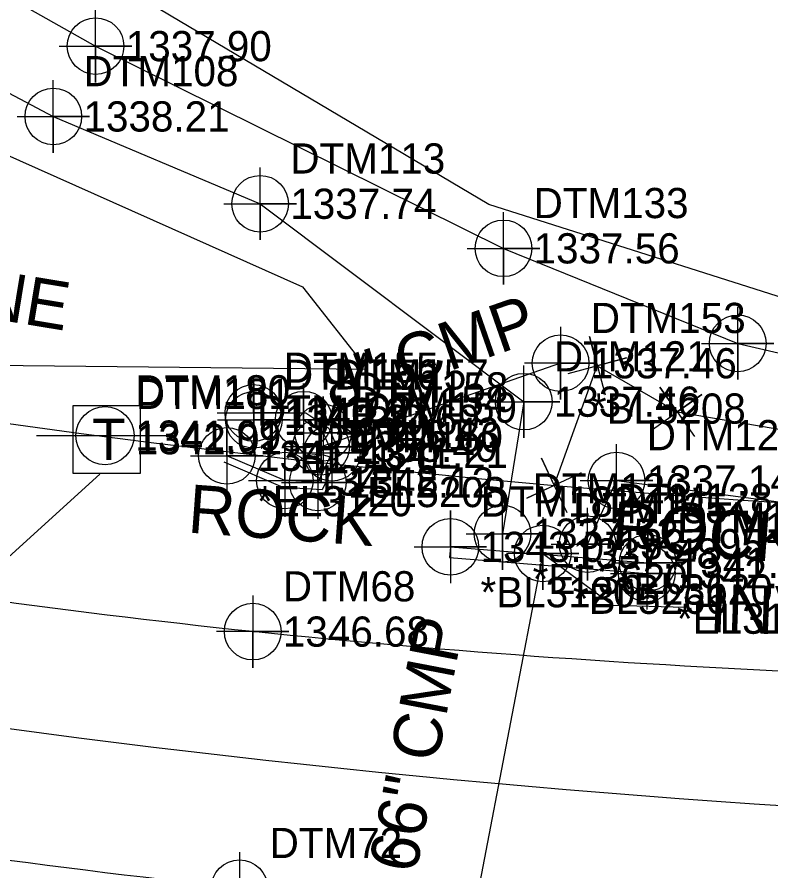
# Model space of a CAD drawing. Extents: x 1303760 to 1305114, y 904598 to 905144.
# Drawn here: x 1304141.1 to 1304203.5, y 904815.9 to 904886.6 of the extents above; entities that cross this region are included whole.
import ezdxf

# ---------------------------------------------------------------- set-up
doc = ezdxf.new("R2010")
doc.units = 0
for name, color, linetype in [('Exist Horizontal Alignment', 7, 'Continuous'), ('Exist Hydro Jurisdictional Stream or Body of Water', 7, 'Continuous'), ('Exist Hydro Stream or Body of Water Cogo Comment', 7, 'Continuous'), ('Exist Hydro Stream or Body of Water Cogo Elevation', 7, 'Continuous'), ('Exist Hydro Stream or Body of Water Cogo Number', 7, 'Continuous'), ('Exist Hydro Stream or Body of Water Cogo Point CELL', 7, 'Continuous'), ('Exist Property Corner CELL', 7, 'Continuous'), ('Exist Property Line', 7, 'Continuous'), ('Exist Right of Way Line', 7, 'Continuous'), ('Exist Roads EOP', 7, 'Continuous'), ('Exist Roads EOP Cogo Elevation', 7, 'Continuous'), ('Exist Roads EOP Cogo Number', 7, 'Continuous'), ('Exist Roads EOP Cogo Point CELL', 7, 'Continuous'), ('Exist Structure Minor Head and End Wall', 7, 'Continuous'), ('Exist Structure Minor Head and End Wall Cogo Comment', 7, 'Continuous'), ('Exist Structure Minor Head and End Wall Cogo Elevation', 7, 'Continuous'), ('Exist Structure Minor Head and End Wall Cogo Number', 7, 'Continuous'), ('Exist Structure Minor Head and End Wall Cogo Point CELL', 7, 'Continuous'), ('Exist Structure Minor Head and End Wall Text', 7, 'Continuous'), ('Exist Structure Minor Pipes CMP 66 Inch', 7, 'Continuous'), ('Exist Structure Minor Pipes CMP 66 Inch Cogo Comment', 7, 'Continuous'), ('Exist Structure Minor Pipes CMP 66 Inch Cogo Elevation', 7, 'Continuous'), ('Exist Structure Minor Pipes CMP 66 Inch Cogo Number', 7, 'Continuous'), ('Exist Structure Minor Pipes CMP 66 Inch Cogo Point CELL', 7, 'Continuous'), ('Exist Structure Minor Pipes CMP 66 Inch Invert', 7, 'Continuous'), ('Exist Structure Minor Pipes CMP 66 Inch Text', 7, 'Continuous'), ('Exist Structure Minor Pipes CMP 8 Inch', 7, 'Continuous'), ('Exist Structure Minor Pipes CMP 8 Inch Cogo Comment', 7, 'Continuous'), ('Exist Structure Minor Pipes CMP 8 Inch Cogo Elevation', 7, 'Continuous'), ('Exist Structure Minor Pipes CMP 8 Inch Cogo Number', 7, 'Continuous'), ('Exist Structure Minor Pipes CMP 8 Inch Cogo Point CELL', 7, 'Continuous'), ('Exist Structure Minor Pipes CMP 8 Inch Text', 7, 'Continuous'), ('Exist Utilities Telephone Pedestal CELL', 7, 'Continuous'), ('Exist Utilities Telephone Pedestal Cogo Elevation', 7, 'Continuous'), ('Exist Utilities Telephone Pedestal Cogo Number', 7, 'Continuous'), ('Exist Utilities Telephone Pole CELL', 7, 'Continuous'), ('Exist Utilities Telephone Pole Cogo Elevation', 7, 'Continuous'), ('Exist Utilities Telephone Pole Cogo Number', 7, 'Continuous'), ('Exist Utilities Telephone Pole Text', 7, 'Continuous'), ('Exist Utilities Telephone UG Cable', 7, 'Continuous'), ('Exist Vegetation Woods Line', 7, 'Continuous'), ('Old_Level_20', 7, 'Continuous')]:
    doc.layers.add(name, color=color, linetype=linetype)

msp = doc.modelspace()

# ---------------------------------------------------------------- linework, layer by layer
at = {"layer": 'Exist Horizontal Alignment'}
msp.add_arc((1304263.288, 905736.164), 916.732, 256.225985, 268.713275, dxfattribs=at)
at = {"layer": 'Exist Hydro Jurisdictional Stream or Body of Water'}
for points in [[(1304086.737, 904920.467), (1304117.246, 904901.303), (1304147.629, 904884.176), (1304181.384, 904867.439), (1304200.772, 904859.571), (1304219.149, 904855.326), (1304237.904, 904861.515), (1304264.914, 904869.609), (1304261.855, 904877.782), (1304240.828, 904891.776), (1304226.533, 904914.525), (1304213.592, 904933.12)], [(1304075.423, 904915.625), (1304102.884, 904899.213), (1304116.452, 904893.027), (1304144.133, 904878.357), (1304161.248, 904871.13), (1304183.062, 904854.749), (1304181.303, 904843.822)], [(1304188.34, 904842.952), (1304190.745, 904848.229), (1304219.476, 904844.44), (1304237.496, 904851.466), (1304256.984, 904856.751), (1304268.533, 904856.105), (1304285.953, 904843.45), (1304293.957, 904833.945)]]:
    msp.add_lwpolyline(points, dxfattribs=at)
at = {"layer": 'Exist Hydro Stream or Body of Water Cogo Point CELL'}
for points in [[(1304144.629, 904884.176), (1304150.629, 904884.176), (1304147.629, 904884.176), (1304147.629, 904881.176), (1304147.629, 904887.176)], [(1304141.133, 904878.357), (1304147.133, 904878.357), (1304144.133, 904878.357), (1304144.133, 904875.357), (1304144.133, 904881.357)], [(1304158.248, 904871.13), (1304164.248, 904871.13), (1304161.248, 904871.13), (1304161.248, 904868.13), (1304161.248, 904874.13)], [(1304178.384, 904867.439), (1304184.384, 904867.439), (1304181.384, 904867.439), (1304181.384, 904864.439), (1304181.384, 904870.439)], [(1304197.772, 904859.571), (1304203.772, 904859.571), (1304200.772, 904859.571), (1304200.772, 904856.571), (1304200.772, 904862.571)], [(1304180.062, 904854.749), (1304186.062, 904854.749), (1304183.062, 904854.749), (1304183.062, 904851.749), (1304183.062, 904857.749)], [(1304187.745, 904848.229), (1304193.745, 904848.229), (1304190.745, 904848.229), (1304190.745, 904845.229), (1304190.745, 904851.229)], [(1304178.303, 904843.822), (1304184.303, 904843.822), (1304181.303, 904843.822), (1304181.303, 904840.822), (1304181.303, 904846.822)], [(1304185.34, 904842.952), (1304191.34, 904842.952), (1304188.34, 904842.952), (1304188.34, 904839.952), (1304188.34, 904845.952)]]:
    msp.add_lwpolyline(points, dxfattribs=at)
for centre in [(1304147.629, 904884.176), (1304144.133, 904878.357), (1304161.248, 904871.13), (1304181.384, 904867.439), (1304200.772, 904859.571), (1304183.062, 904854.749), (1304190.745, 904848.229), (1304181.303, 904843.822), (1304188.34, 904842.952)]:
    msp.add_circle(centre, 2.344, dxfattribs=at)
at = {"layer": 'Exist Property Corner CELL'}
for p, q in [((1304189.143, 904857.72), (1304189.143, 904857.72)), ((1304195.759, 904853.9), (1304195.759, 904853.9)), ((1304185.586, 904847.823), (1304185.586, 904847.823))]:
    msp.add_line(p, q, dxfattribs=at)
for points in [[(1304186.728, 904857.073), (1304191.558, 904858.367), (1304189.143, 904857.72), (1304188.496, 904860.135), (1304189.79, 904855.305)], [(1304193.719, 904852.455), (1304197.798, 904855.345), (1304195.759, 904853.9), (1304194.313, 904855.94), (1304197.204, 904851.86)], [(1304186.651, 904845.561), (1304184.52, 904850.084), (1304185.586, 904847.823), (1304183.324, 904846.757), (1304187.847, 904848.889)]]:
    msp.add_lwpolyline(points, dxfattribs=at)
at = {"layer": 'Exist Property Line'}
for p, q in [((1304185.586, 904847.823), (1304189.143, 904857.72)), ((1304189.143, 904857.72), (1304195.759, 904853.9)), ((1304195.759, 904853.9), (1304219.313, 904849.883))]:
    msp.add_line(p, q, dxfattribs=at)
at = {"layer": 'Exist Right of Way Line'}
for radius in [891.732, 941.732]:
    msp.add_arc((1304263.288, 905736.164), radius, 256.225985, 268.713275, dxfattribs=at)
at = {"layer": 'Exist Roads EOP'}
for points in [[(1304247.269, 904830.948), (1304210.379, 904832.153), (1304160.634, 904835.718), (1304112.61, 904842.451), (1304065.371, 904851.73)], [(1304262.029, 904807.84), (1304208.937, 904810.393), (1304159.538, 904814.474), (1304108.782, 904821.63), (1304061.002, 904830.952)]]:
    msp.add_spline(points, degree=3, dxfattribs=at)
at = {"layer": 'Exist Roads EOP Cogo Point CELL'}
for points in [[(1304160.634, 904838.718), (1304160.634, 904832.718), (1304160.634, 904835.718), (1304163.634, 904835.718), (1304157.634, 904835.718)], [(1304159.538, 904817.474), (1304159.538, 904811.474), (1304159.538, 904814.474), (1304162.538, 904814.474), (1304156.538, 904814.474)]]:
    msp.add_lwpolyline(points, dxfattribs=at)
for centre in [(1304160.634, 904835.718), (1304159.538, 904814.474)]:
    msp.add_circle(centre, 2.344, dxfattribs=at)
at = {"layer": 'Exist Structure Minor Head and End Wall'}
for p, q in [((1304160.691, 904853.818), (1304165.024, 904853.836)), ((1304165.024, 904853.836), (1304166.926, 904852.567)), ((1304166.926, 904852.567), (1304167.824, 904850.498)), ((1304167.824, 904850.498), (1304166.37, 904847.463)), ((1304163.16, 904847.648), (1304158.269, 904849.732)), ((1304166.37, 904847.463), (1304163.16, 904847.648)), ((1304176.989, 904842.729), (1304176.908, 904841.85)), ((1304176.908, 904841.85), (1304193.253, 904840.537))]:
    msp.add_line(p, q, dxfattribs=at)
for points in [[(1304160.691, 904853.818), (1304160.722, 904853.239)], [(1304160.722, 904853.239), (1304164.85, 904853.256)], [(1304164.85, 904853.256), (1304166.463, 904852.18)], [(1304166.463, 904852.18), (1304167.188, 904850.51)], [(1304163.294, 904848.22), (1304158.496, 904850.264)], [(1304167.188, 904850.51), (1304166.016, 904848.063)], [(1304166.016, 904848.063), (1304163.294, 904848.22)], [(1304176.989, 904842.729), (1304193.324, 904841.417)], [(1304193.324, 904841.417), (1304193.243, 904840.538)]]:
    msp.add_lwpolyline(points, dxfattribs=at)
at = {"layer": 'Exist Structure Minor Head and End Wall Cogo Point CELL'}
for points in [[(1304157.691, 904853.817), (1304163.691, 904853.817), (1304160.691, 904853.817), (1304160.691, 904856.817), (1304160.691, 904850.817)], [(1304157.722, 904853.239), (1304163.722, 904853.239), (1304160.722, 904853.239), (1304160.722, 904856.239), (1304160.722, 904850.239)], [(1304161.85, 904853.256), (1304167.85, 904853.256), (1304164.85, 904853.256), (1304164.85, 904856.256), (1304164.85, 904850.256)], [(1304163.463, 904852.18), (1304169.463, 904852.18), (1304166.463, 904852.18), (1304166.463, 904855.18), (1304166.463, 904849.18)], [(1304155.496, 904850.264), (1304161.496, 904850.264), (1304158.496, 904850.264), (1304158.496, 904853.264), (1304158.496, 904847.264)], [(1304164.188, 904850.51), (1304170.188, 904850.51), (1304167.188, 904850.51), (1304167.188, 904853.51), (1304167.188, 904847.51)], [(1304160.294, 904848.22), (1304166.294, 904848.22), (1304163.294, 904848.22), (1304163.294, 904851.22), (1304163.294, 904845.22)], [(1304163.016, 904848.063), (1304169.016, 904848.063), (1304166.016, 904848.063), (1304166.016, 904851.063), (1304166.016, 904845.063)], [(1304173.989, 904842.729), (1304179.989, 904842.729), (1304176.989, 904842.729), (1304176.989, 904845.729), (1304176.989, 904839.729)], [(1304190.324, 904841.417), (1304196.324, 904841.417), (1304193.324, 904841.417), (1304193.324, 904844.417), (1304193.324, 904838.417)], [(1304190.243, 904840.538), (1304196.243, 904840.538), (1304193.243, 904840.538), (1304193.243, 904843.538), (1304193.243, 904837.538)]]:
    msp.add_lwpolyline(points, dxfattribs=at)
for centre in [(1304160.691, 904853.817), (1304160.722, 904853.239), (1304164.85, 904853.256), (1304166.463, 904852.18), (1304167.188, 904850.51), (1304158.496, 904850.264), (1304163.294, 904848.22), (1304166.016, 904848.063), (1304176.989, 904842.729), (1304193.324, 904841.417), (1304193.243, 904840.538)]:
    msp.add_circle(centre, 2.344, dxfattribs=at)
at = {"layer": 'Exist Structure Minor Pipes CMP 66 Inch'}
msp.add_line((1304184.634, 904842.186), (1304176.943, 904802.084), dxfattribs=at)
at = {"layer": 'Exist Structure Minor Pipes CMP 66 Inch Cogo Point CELL'}
msp.add_lwpolyline([(1304184.634, 904845.186), (1304184.634, 904839.186), (1304184.634, 904842.186), (1304187.634, 904842.186), (1304181.634, 904842.186)], dxfattribs=at)
msp.add_circle((1304184.634, 904842.186), 2.344, dxfattribs=at)
at = {"layer": 'Exist Structure Minor Pipes CMP 66 Inch Invert'}
msp.add_lwpolyline([(1304184.634, 904842.186), (1304190.432, 904837.911), (1304196.43, 904837.739)], dxfattribs=at)
at = {"layer": 'Exist Structure Minor Pipes CMP 8 Inch'}
msp.add_line((1304186.115, 904857.929), (1304166.29, 904851.019), dxfattribs=at)
at = {"layer": 'Exist Structure Minor Pipes CMP 8 Inch Cogo Point CELL'}
for points in [[(1304186.115, 904860.929), (1304186.115, 904854.929), (1304186.115, 904857.929), (1304189.115, 904857.929), (1304183.115, 904857.929)], [(1304166.29, 904854.019), (1304166.29, 904848.019), (1304166.29, 904851.019), (1304169.29, 904851.019), (1304163.29, 904851.019)]]:
    msp.add_lwpolyline(points, dxfattribs=at)
for centre in [(1304186.115, 904857.929), (1304166.29, 904851.019)]:
    msp.add_circle(centre, 2.344, dxfattribs=at)
at = {"layer": 'Exist Utilities Telephone Pedestal CELL'}
msp.add_line((1304148.465, 904851.647), (1304148.465, 904851.647), dxfattribs=at)
msp.add_lwpolyline([(1304145.741, 904848.821), (1304151.335, 904848.821), (1304151.335, 904854.416), (1304145.741, 904854.416), (1304145.741, 904848.821)], dxfattribs=at)
at = {"layer": 'Exist Utilities Telephone Pole CELL'}
for p, q in [((1304142.735, 904851.937), (1304154.073, 904851.937)), ((1304148.41, 904851.937), (1304148.41, 904851.937))]:
    msp.add_line(p, q, dxfattribs=at)
msp.add_circle((1304148.41, 904851.937), 2.407, dxfattribs=at)
at = {"layer": 'Exist Utilities Telephone UG Cable'}
msp.add_lwpolyline([(1304147.995, 904848.758), (1304138.571, 904840.216), (1304063.599, 904855.443)], dxfattribs=at)
at = {"layer": 'Exist Vegetation Woods Line'}
for points in [[(1304203.856, 904938.589), (1304225.022, 904907.703), (1304240.09, 904882.563), (1304259.104, 904871.429), (1304258.745, 904873.584), (1304256.234, 904870.711), (1304261.615, 904869.993), (1304226.099, 904864.605), (1304211.748, 904861.014), (1304180.178, 904871.07), (1304086.902, 904926.378)], [(1304066.095, 904912.731), (1304102.687, 904891.541), (1304138.204, 904876.098), (1304164.752, 904864.246), (1304170.133, 904857.423), (1304136.41, 904857.782), (1304031.295, 904880.408)]]:
    msp.add_lwpolyline(points, dxfattribs=at)
at = {"layer": 'Old_Level_20'}
msp.add_arc((1304263.288, 905736.164), 916.732, 256.225985, 268.713275, dxfattribs=at)

# ---------------------------------------------------------------- texts
at = {"layer": 'Exist Hydro Stream or Body of Water Cogo Comment'}
for s, p in [('*EL3620', (1304183.803, 904838.822)), ('*BL3620', (1304190.84, 904837.952))]:
    msp.add_text(s, height=2.5, dxfattribs=at).set_placement(p)
at = {"layer": 'Exist Hydro Stream or Body of Water Cogo Elevation'}
for s, p in [('1337.90', (1304150.129, 904882.926)), ('1338.21', (1304146.633, 904877.107)), ('1337.74', (1304163.748, 904869.88)), ('1337.56', (1304183.884, 904866.189)), ('1337.46', (1304185.562, 904853.499)), ('1337.14', (1304193.245, 904846.979)), ('1337.52', (1304183.803, 904842.572)), ('1337.95', (1304190.84, 904841.702))]:
    msp.add_text(s, height=2.5, dxfattribs=at).set_placement(p)
at = {"layer": 'Exist Hydro Stream or Body of Water Cogo Number'}
for s, p in [('DTM108', (1304146.633, 904880.857)), ('DTM113', (1304163.748, 904873.63)), ('DTM133', (1304183.884, 904869.939)), ('DTM121', (1304185.562, 904857.249)), ('DTM129', (1304193.245, 904850.729)), ('DTM126', (1304183.803, 904846.322)), ('DTM128', (1304190.84, 904845.452))]:
    msp.add_text(s, height=2.5, dxfattribs=at).set_placement(p)
at = {"layer": 'Exist Roads EOP Cogo Elevation'}
msp.add_text('1346.68', height=2.5, dxfattribs=at).set_placement((1304163.134, 904834.468))
at = {"layer": 'Exist Roads EOP Cogo Number'}
for s, p in [('DTM68', (1304163.134, 904838.218)), ('DTM72', (1304162.038, 904816.974))]:
    msp.add_text(s, height=2.5, dxfattribs=at).set_placement(p)
at = {"layer": 'Exist Structure Minor Head and End Wall Cogo Comment'}
for s, p in [('*BL3120', (1304163.191, 904848.817)), ('*EL3120', (1304160.996, 904845.264)), ('*BL3120', (1304179.489, 904837.729)), ('*EL3120', (1304195.743, 904835.538))]:
    msp.add_text(s, height=2.5, dxfattribs=at).set_placement(p)
at = {"layer": 'Exist Structure Minor Head and End Wall Cogo Elevation'}
for s, p in [('1340.33', (1304163.191, 904852.567)), ('1340.34', (1304163.222, 904851.989)), ('1340.69', (1304167.35, 904852.006)), ('1341.43', (1304168.963, 904850.93)), ('1341.43', (1304160.996, 904849.014)), ('1341.21', (1304169.688, 904849.26)), ('1341.87', (1304165.794, 904846.97)), ('1342.12', (1304168.516, 904846.813)), ('1343.07', (1304179.489, 904841.479)), ('1341.97', (1304195.824, 904840.167)), ('1342.11', (1304195.743, 904839.288))]:
    msp.add_text(s, height=2.5, dxfattribs=at).set_placement(p)
at = {"layer": 'Exist Structure Minor Head and End Wall Cogo Number'}
for s, p in [('DTM155', (1304163.191, 904856.317)), ('DTM156', (1304163.222, 904855.739)), ('DTM157', (1304167.35, 904855.756)), ('DTM158', (1304168.963, 904854.68)), ('DTM162', (1304160.996, 904852.764)), ('DTM159', (1304169.688, 904853.01)), ('DTM161', (1304165.794, 904850.72)), ('DTM160', (1304168.516, 904850.563)), ('DTM182', (1304179.489, 904845.229)), ('DTM183', (1304195.824, 904843.917)), ('DTM184', (1304195.743, 904843.038))]:
    msp.add_text(s, height=2.5, dxfattribs=at).set_placement(p)
at = {"layer": 'Exist Structure Minor Head and End Wall Text'}
for s, rotation, p in [('ROCK', 355.78126, (1304155.192, 904843.92)), ('ROCK HW', 355.70057, (1304190.238, 904842.518))]:
    msp.add_text(s, height=4, rotation=rotation, dxfattribs=at).set_placement(p)
at = {"layer": 'Exist Structure Minor Pipes CMP 66 Inch Cogo Comment'}
msp.add_text('*BL5266', height=2.5, dxfattribs=at).set_placement((1304187.134, 904837.186))
at = {"layer": 'Exist Structure Minor Pipes CMP 66 Inch Cogo Elevation'}
msp.add_text('1337.48', height=2.5, dxfattribs=at).set_placement((1304187.134, 904840.936))
at = {"layer": 'Exist Structure Minor Pipes CMP 66 Inch Cogo Number'}
msp.add_text('DTM135', height=2.5, dxfattribs=at).set_placement((1304187.134, 904844.686))
at = {"layer": 'Exist Structure Minor Pipes CMP 66 Inch Invert'}
msp.add_text("INV=1337.48'", height=4, rotation=357.94825, dxfattribs=at).set_placement((1304198.36, 904835.698))
at = {"layer": 'Exist Structure Minor Pipes CMP 66 Inch Text'}
msp.add_text('66" CMP', height=4, rotation=79.1433, dxfattribs=at).set_placement((1304174.141, 904815.614))
at = {"layer": 'Exist Structure Minor Pipes CMP 8 Inch Cogo Comment'}
for s, p in [('*BL5208', (1304188.615, 904852.929)), ('*EL5208', (1304168.79, 904846.019))]:
    msp.add_text(s, height=2.5, dxfattribs=at).set_placement(p)
at = {"layer": 'Exist Structure Minor Pipes CMP 8 Inch Cogo Elevation'}
for s, p in [('1337.46', (1304188.615, 904856.679)), ('1338.40', (1304168.79, 904849.769))]:
    msp.add_text(s, height=2.5, dxfattribs=at).set_placement(p)
at = {"layer": 'Exist Structure Minor Pipes CMP 8 Inch Cogo Number'}
for s, p in [('DTM153', (1304188.615, 904860.429)), ('DTM154', (1304168.79, 904853.519))]:
    msp.add_text(s, height=2.5, dxfattribs=at).set_placement(p)
at = {"layer": 'Exist Structure Minor Pipes CMP 8 Inch Text'}
msp.add_text('8" CMP', height=4, rotation=19.21599, dxfattribs=at).set_placement((1304167.227, 904853.887))
at = {"layer": 'Exist Utilities Telephone Pedestal CELL'}
msp.add_text('T', height=3.42, dxfattribs=at).set_placement((1304147.334, 904849.934))
at = {"layer": 'Exist Utilities Telephone Pedestal Cogo Elevation'}
msp.add_text('1342.01', height=2.5, dxfattribs=at).set_placement((1304150.965, 904850.397))
at = {"layer": 'Exist Utilities Telephone Pedestal Cogo Number'}
msp.add_text('DTM181', height=2.5, dxfattribs=at).set_placement((1304150.965, 904854.147))
at = {"layer": 'Exist Utilities Telephone Pole Cogo Elevation'}
msp.add_text('1341.99', height=2.5, dxfattribs=at).set_placement((1304150.91, 904850.687))
at = {"layer": 'Exist Utilities Telephone Pole Cogo Number'}
msp.add_text('DTM180', height=2.5, dxfattribs=at).set_placement((1304150.91, 904854.437))
at = {"layer": 'Exist Utilities Telephone Pole Text'}
msp.add_text('TELEPHONE', height=4, rotation=350.64937, dxfattribs=at).set_placement((1304113.139, 904865.879))

doc.saveas('drawing.dxf')
